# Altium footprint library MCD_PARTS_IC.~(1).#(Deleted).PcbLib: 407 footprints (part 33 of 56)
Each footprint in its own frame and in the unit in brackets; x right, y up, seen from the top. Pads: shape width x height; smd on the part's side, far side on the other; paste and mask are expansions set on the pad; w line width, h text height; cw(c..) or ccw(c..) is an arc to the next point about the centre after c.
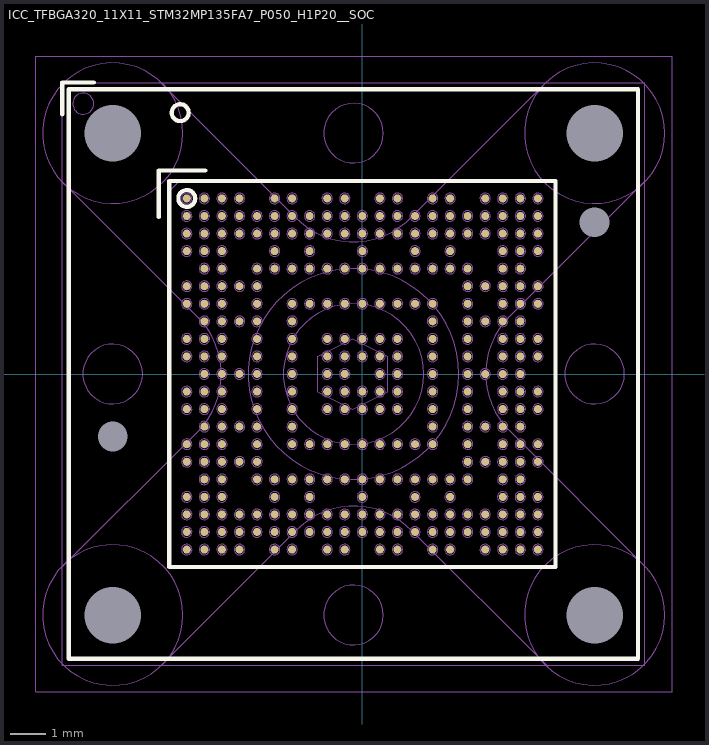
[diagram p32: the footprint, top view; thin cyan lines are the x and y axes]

## ICC_TFBGA320_11X11_STM32MP135FA7_P050_H1P20__SOCKET_IRONWOOD_SG-BGA-7074MF [mm] "MCD-02251"
height 1.2
pads (326):
  round 0.23 smd paste+0.025 mask+0.05: A1(-5,5) A2(-4.5,5) A3(-4,5) A4(-3.5,5) A6(-2.5,5) A7(-2,5) A9(-1,5) A10(-0.5,5) A12(0.5,5) A13(1,5) A15(2,5) A16(2.5,5) A18(3.5,5) A19(4,5) A20(4.5,5) A21(5,5) AA1(-5,-5) AA2(-4.5,-5) AA3(-4,-5) AA4(-3.5,-5) AA6(-2.5,-5) AA7(-2,-5) AA9(-1,-5) AA10(-0.5,-5) AA12(0.5,-5) AA13(1,-5) AA15(2,-5) AA16(2.5,-5) AA18(3.5,-5) AA19(4,-5) AA20(4.5,-5) AA21(5,-5) B1(-5,4.5) B2(-4.5,4.5) B3(-4,4.5) B4(-3.5,4.5) B5(-3,4.5) B6(-2.5,4.5) B7(-2,4.5) B8(-1.5,4.5) B9(-1,4.5) B10(-0.5,4.5) B11(0,4.5) B12(0.5,4.5) B13(1,4.5) B14(1.5,4.5) B15(2,4.5) B16(2.5,4.5) B17(3,4.5) B18(3.5,4.5) B19(4,4.5) B20(4.5,4.5) B21(5,4.5) C1(-5,4) C2(-4.5,4) C3(-4,4) C4(-3.5,4) C5(-3,4) C6(-2.5,4) C7(-2,4) C8(-1.5,4) C9(-1,4) C10(-0.5,4) C11(0,4) C12(0.5,4) C13(1,4) C14(1.5,4) C15(2,4) C16(2.5,4) C17(3,4) C18(3.5,4) C19(4,4) C20(4.5,4) C21(5,4) D1(-5,3.5) D2(-4.5,3.5) D3(-4,3.5) D6(-2.5,3.5) D8(-1.5,3.5) D11(0,3.5) D14(1.5,3.5) D16(2.5,3.5) D19(4,3.5) D20(4.5,3.5) D21(5,3.5) E2(-4.5,3) E3(-4,3) E5(-3,3) E6(-2.5,3) E7(-2,3) E8(-1.5,3) E9(-1,3) E10(-0.5,3) E11(0,3) E12(0.5,3) E13(1,3) E14(1.5,3) E15(2,3) E16(2.5,3) E17(3,3) E19(4,3) E20(4.5,3) F1(-5,2.5) F2(-4.5,2.5) F3(-4,2.5) F4(-3.5,2.5) F5(-3,2.5) F17(3,2.5) F18(3.5,2.5) F19(4,2.5) F20(4.5,2.5) F21(5,2.5) G1(-5,2) G2(-4.5,2) G3(-4,2) G5(-3,2) G7(-2,2) G8(-1.5,2) G9(-1,2) G10(-0.5,2) G11(0,2) G12(0.5,2) G13(1,2) G14(1.5,2) G15(2,2) G17(3,2) G19(4,2) G20(4.5,2) G21(5,2) H2(-4.5,1.5) H3(-4,1.5) H4(-3.5,1.5) H5(-3,1.5) H7(-2,1.5) H15(2,1.5) H17(3,1.5) H18(3.5,1.5) H19(4,1.5) H20(4.5,1.5) J1(-5,1) J2(-4.5,1) J3(-4,1) J5(-3,1) J7(-2,1) J9(-1,1) J10(-0.5,1) J11(0,1) J12(0.5,1) J13(1,1) J15(2,1) J17(3,1) J19(4,1) J20(4.5,1) J21(5,1) K1(-5,0.5) K2(-4.5,0.5) K3(-4,0.5) K5(-3,0.5) K7(-2,0.5) K9(-1,0.5) K10(-0.5,0.5) K11(0,0.5) K12(0.5,0.5) K13(1,0.5) K15(2,0.5) K17(3,0.5) K19(4,0.5) K20(4.5,0.5) K21(5,0.5) L2(-4.5,0) L3(-4,0) L4(-3.5,0) L5(-3,0) L7(-2,0) L9(-1,0) L10(-0.5,0) L12(0.5,0) L13(1,0) L15(2,0) L17(3,0) L18(3.5,0) L19(4,0) L20(4.5,0) M1(-5,-0.5) M2(-4.5,-0.5) M3(-4,-0.5) M5(-3,-0.5) M7(-2,-0.5) M9(-1,-0.5) M10(-0.5,-0.5) M11(0,-0.5) M12(0.5,-0.5) M13(1,-0.5) M15(2,-0.5) M17(3,-0.5) M19(4,-0.5) M20(4.5,-0.5) M21(5,-0.5) N1(-5,-1) N2(-4.5,-1) N3(-4,-1) N5(-3,-1) N7(-2,-1) N9(-1,-1) N10(-0.5,-1) N11(0,-1) N12(0.5,-1) N13(1,-1) N15(2,-1) N17(3,-1) N19(4,-1) N20(4.5,-1) N21(5,-1) P2(-4.5,-1.5) P3(-4,-1.5) P4(-3.5,-1.5) P5(-3,-1.5) P7(-2,-1.5) P15(2,-1.5) P17(3,-1.5) P18(3.5,-1.5) P19(4,-1.5) P20(4.5,-1.5) R1(-5,-2) R2(-4.5,-2) R3(-4,-2) R5(-3,-2) R7(-2,-2) R8(-1.5,-2) R9(-1,-2) R10(-0.5,-2) R11(0,-2) R12(0.5,-2) R13(1,-2) R14(1.5,-2) R15(2,-2) R17(3,-2) R19(4,-2) R20(4.5,-2) R21(5,-2) T1(-5,-2.5) T2(-4.5,-2.5) T3(-4,-2.5) T4(-3.5,-2.5) T5(-3,-2.5) T17(3,-2.5) T18(3.5,-2.5) T19(4,-2.5) T20(4.5,-2.5) T21(5,-2.5) U2(-4.5,-3) U3(-4,-3) U5(-3,-3) U6(-2.5,-3) U7(-2,-3) U8(-1.5,-3) U9(-1,-3) U10(-0.5,-3) U11(0,-3) U12(0.5,-3) U13(1,-3) U14(1.5,-3) U15(2,-3) U16(2.5,-3) U17(3,-3) U19(4,-3) U20(4.5,-3) V1(-5,-3.5) V2(-4.5,-3.5) V3(-4,-3.5) V6(-2.5,-3.5) V8(-1.5,-3.5) V11(-0.001,-3.5) V14(1.5,-3.5) V16(2.5,-3.5) V19(4,-3.5) V20(4.5,-3.5) V21(5,-3.5) W1(-5,-4) W2(-4.5,-4) W3(-4,-4) W4(-3.5,-4) W5(-3,-4) W6(-2.5,-4) W7(-2,-4) W8(-1.5,-4) W9(-1,-4) W10(-0.5,-4) W11(0,-4) W12(0.5,-4) W13(1,-4) W14(1.5,-4) W15(2,-4) W16(2.5,-4) W17(3,-4) W18(3.5,-4) W19(4,-4) W20(4.5,-4) W21(5,-4) Y1(-5,-4.5) Y2(-4.5,-4.5) Y3(-4,-4.5) Y4(-3.5,-4.5) Y5(-3,-4.5) Y6(-2.5,-4.5) Y7(-2,-4.5) Y8(-1.5,-4.5) Y9(-1,-4.5) Y10(-0.5,-4.5) Y11(0,-4.5) Y12(0.5,-4.5) Y13(1,-4.5) Y14(1.5,-4.5) Y15(2,-4.5) Y16(2.5,-4.5) Y17(3,-4.5) Y18(3.5,-4.5) Y19(4,-4.5) Y20(4.5,-4.5) Y21(5,-4.5)
  round 0 hole 0.85 unplated mask+0.05: NPTH1(6.615,4.32) NPTH2(-7.11,-1.785)
  round 0 hole 1.61 unplated mask+0.05: PTH1(-7.11,6.86) PTH2(6.615,6.86) PTH3(6.615,-6.865) PTH4(-7.11,-6.865)
Top Layer:
  lines w0.1: 4.5,2.5 ccw(c4.5,2.5) 4.5,2.5
Top Overlay:
  circle w0.12: c-5,5 r0.24
  circle w0.12: c-5.187,7.444 r0.24
  lines w0.12: -8.55,7.4 -8.55,8.3 -7.65,8.3 ; -5.8,4.475 -5.8,5.8 -4.475,5.8 ; -8.36,-8.112 -8.36,8.11 7.85,8.11 7.85,-8.112 -8.36,-8.112 ; -5.5,-5.5 -5.5,5.5 5.5,5.5 5.5,-5.5 -5.5,-5.5
Bottom Overlay:
  circle w0.12: c-7.11,-6.865 r2
  circle w0.12: c6.615,-6.865 r2
  circle w0.12: c6.615,6.86 r2
  circle w0.12: c-7.11,6.86 r2
  circle w0.12: c-0.25,0 r2
  lines w0.12: -8.575,-5.525 -4.723,-1.673 ; -8.575,5.5 -4.75,1.675 cw(c-6.312,-0.013) -4.722,-1.674 ; -5.775,8.325 -1.923,4.473 ; -5.75,-8.325 -1.925,-4.5 cw(c-0.237,-6.062) 1.424,-4.472 ; -1.924,4.472 ccw(c-0.263,6.063) 1.425,4.5 5.25,8.325 ; 1.423,-4.473 5.275,-8.325 ; 4.222,1.674 ccw(c5.813,0.013) 4.25,-1.675 8.075,-5.5 ; 4.223,1.673 8.075,5.525
M8-Bottom Info:
  circle w0.01: c-0.25,0 r2
  circle w0.01: c-7.11,6.86 r2
  circle w0.01: c6.615,6.86 r2
  circle w0.01: c6.615,-6.865 r2
  circle w0.01: c-7.11,-6.865 r2
  lines w0.01: -8.575,-5.525 -4.723,-1.673 ; -8.575,5.5 -4.75,1.675 cw(c-6.312,-0.013) -4.722,-1.674 ; -5.775,8.325 -1.923,4.473 ; -5.75,-8.325 -1.925,-4.5 cw(c-0.237,-6.062) 1.424,-4.472 ; -1.924,4.472 ccw(c-0.263,6.063) 1.425,4.5 5.25,8.325 ; 1.423,-4.473 5.275,-8.325 ; 4.222,1.674 ccw(c5.813,0.013) 4.25,-1.675 8.075,-5.5 ; 4.223,1.673 8.075,5.525
  text "Max Height :" at -3.9,2.475 h1.52
  text "1.5mm" at -2.35,-3.25 h1.52
M14-Top Assembly:
  drawing of 345 lines, arcs and shapes, not listed
  text "A1" at -5.25,4.8 h0.4
  text "'.Designator'" at 0,0 h0.75
M15-Bottom Assembly:
  circle w0.01: c-7.11,6.86 r2
  circle w0.01: c-0.25,0 r2
  circle w0.01: c6.615,6.86 r2
  circle w0.01: c6.615,-6.865 r2
  circle w0.01: c-7.11,-6.865 r2
  lines w0.01: -8.575,-5.525 -4.723,-1.673 ; -8.575,5.5 -4.75,1.675 cw(c-6.312,-0.013) -4.722,-1.674 ; -5.775,8.325 -1.923,4.473 ; -5.75,-8.325 -1.925,-4.5 cw(c-0.237,-6.062) 1.424,-4.472 ; -1.924,4.472 ccw(c-0.263,6.063) 1.425,4.5 5.25,8.325 ; 1.423,-4.473 5.275,-8.325 ; 4.222,1.674 ccw(c5.813,0.013) 4.25,-1.675 8.075,-5.5 ; 4.223,1.673 8.075,5.525
M16-Top Courtyard:
  lines w0.01: -8.55,-8.3 8.05,-8.3 8.05,8.3 -8.55,8.3 -8.55,-8.3
M17-Bottom Courtyard:
  lines w0.01: -9.3,-9.05 -9.3,9.05 8.825,9.05 8.825,-9.05 -9.3,-9.05
3D body: height 6, standoff 5, extent -7.953,-0.848 -6.26,0.849
3D body: height 6, standoff 5, extent -1.093,6.012 0.6,7.709
3D body: height 6, standoff 5, extent 5.772,-0.848 7.465,0.849
3D body: height 6, standoff 5, extent -1.093,-7.713 0.6,-6.017
3D body: height 8.25, standoff 5, extent -3.25,-3 2.75,3
3D body: height 5, standoff 0, extent -8.362,-8.112 7.863,8.113
3D body: height 8.26, standoff 8.25, extent -1.25,-1 0.75,1
3D body: height 1.11, standoff 1.1, extent -5.298,4.701 -4.7,5.3
3D body: height 0.36, standoff -0.04, extent 4.3,-5.197 4.699,-4.803
3D body: height 0.36, standoff -0.04, extent 4.8,-4.697 5.199,-4.303
3D body: height 0.36, standoff -0.04, extent 3.8,-5.197 4.199,-4.803
3D body: height 0.36, standoff -0.04, extent 0.801,-4.697 1.2,-4.303
3D body: height 0.36, standoff -0.04, extent 1.301,-4.697 1.7,-4.303
3D body: height 0.36, standoff -0.04, extent 2.3,-4.697 2.699,-4.303
3D body: height 0.36, standoff -0.04, extent 2.3,-5.197 2.7,-4.803
3D body: height 0.36, standoff -0.04, extent 2.8,-4.697 3.199,-4.303
3D body: height 0.36, standoff -0.04, extent -4.199,-5.197 -3.8,-4.803
3D body: height 0.36, standoff -0.04, extent -4.199,-4.697 -3.8,-4.303
3D body: height 0.36, standoff -0.04, extent -2.199,-4.697 -1.8,-4.303
3D body: height 0.36, standoff -0.04, extent -1.699,-4.697 -1.3,-4.303
3D body: height 0.36, standoff -0.04, extent -0.699,-5.197 -0.3,-4.803
3D body: height 0.36, standoff -0.04, extent 4.3,-4.697 4.699,-4.303
3D body: height 0.36, standoff -0.04, extent 3.8,-4.697 4.199,-4.303
3D body: height 0.36, standoff -0.04, extent 3.3,-5.197 3.7,-4.803
3D body: height 0.36, standoff -0.04, extent -1.199,-5.197 -0.8,-4.803
3D body: height 0.36, standoff -0.04, extent -0.199,-4.697 0.2,-4.303
3D body: height 0.36, standoff -0.04, extent 0.3,-5.197 0.7,-4.803
3D body: height 0.36, standoff -0.04, extent 1.8,-5.197 2.199,-4.803
3D body: height 0.36, standoff -0.04, extent -5.199,-5.197 -4.8,-4.803
3D body: height 0.36, standoff -0.04, extent -4.699,-5.197 -4.3,-4.803
3D body: height 0.36, standoff -0.04, extent -3.699,-5.197 -3.3,-4.803
3D body: height 0.36, standoff -0.04, extent -2.699,-5.197 -2.3,-4.803
3D body: height 0.36, standoff -0.04, extent -2.199,-5.197 -1.8,-4.803
3D body: height 0.36, standoff -0.04, extent 4.8,-5.197 5.199,-4.803
3D body: height 0.36, standoff -0.04, extent 3.3,-4.697 3.699,-4.303
3D body: height 0.36, standoff -0.04, extent -1.199,-4.697 -0.8,-4.303
3D body: height 0.36, standoff -0.04, extent -0.699,-4.697 -0.3,-4.303
3D body: height 0.36, standoff -0.04, extent 0.3,-4.697 0.7,-4.303
3D body: height 0.36, standoff -0.04, extent 0.801,-5.197 1.2,-4.803
3D body: height 0.36, standoff -0.04, extent 1.8,-4.697 2.2,-4.303
3D body: height 0.36, standoff -0.04, extent -5.199,-4.697 -4.8,-4.303
3D body: height 0.36, standoff -0.04, extent -4.699,-4.697 -4.3,-4.303
3D body: height 0.36, standoff -0.04, extent -3.699,-4.697 -3.3,-4.303
3D body: height 0.36, standoff -0.04, extent -3.199,-4.697 -2.8,-4.303
3D body: height 0.36, standoff -0.04, extent -2.699,-4.697 -2.3,-4.303
3D body: height 0.36, standoff -0.04, extent 4.8,-3.697 5.199,-3.303
3D body: height 0.36, standoff -0.04, extent 4.3,-3.697 4.699,-3.303
3D body: height 0.36, standoff -0.04, extent 3.8,-3.697 4.199,-3.303
3D body: height 0.36, standoff -0.04, extent 4.8,-4.197 5.199,-3.803
3D body: height 0.36, standoff -0.04, extent 4.3,-4.197 4.699,-3.803
3D body: height 0.36, standoff -0.04, extent -0.2,-3.697 0.2,-3.303
3D body: height 0.36, standoff -0.04, extent 0.8,-4.197 1.2,-3.803
3D body: height 0.36, standoff -0.04, extent 2.3,-3.697 2.699,-3.303
3D body: height 0.36, standoff -0.04, extent -4.699,-3.697 -4.3,-3.303
3D body: height 0.36, standoff -0.04, extent -4.199,-3.697 -3.8,-3.303
3D body: height 0.36, standoff -0.04, extent -3.199,-4.197 -2.8,-3.803
3D body: height 0.36, standoff -0.04, extent -1.699,-3.697 -1.3,-3.303
3D body: height 0.36, standoff -0.04, extent 4.3,-2.697 4.699,-2.303
3D body: height 0.36, standoff -0.04, extent 3.8,-2.697 4.199,-2.303
3D body: height 0.36, standoff -0.04, extent 4.3,-3.197 4.699,-2.803
3D body: height 0.36, standoff -0.04, extent 3.8,-3.197 4.2,-2.803
3D body: height 0.36, standoff -0.04, extent 2.801,-3.197 3.2,-2.803
3D body: height 0.36, standoff -0.04, extent -1.199,-3.197 -0.8,-2.803
3D body: height 0.36, standoff -0.04, extent 0.801,-3.197 1.2,-2.803
3D body: height 0.36, standoff -0.04, extent 1.3,-3.197 1.7,-2.803
3D body: height 0.36, standoff -0.04, extent 1.8,-3.197 2.2,-2.803
3D body: height 0.36, standoff -0.04, extent 2.3,-3.197 2.699,-2.803
3D body: height 0.36, standoff -0.04, extent -4.699,-3.197 -4.3,-2.803
3D body: height 0.36, standoff -0.04, extent -4.199,-3.197 -3.8,-2.803
3D body: height 0.36, standoff -0.04, extent -3.199,-3.197 -2.8,-2.803
3D body: height 0.36, standoff -0.04, extent -2.199,-3.197 -1.8,-2.803
3D body: height 0.36, standoff -0.04, extent -1.699,-3.197 -1.3,-2.803
3D body: height 0.36, standoff -0.04, extent 4.8,-2.697 5.199,-2.303
3D body: height 0.36, standoff -0.04, extent 4.8,-2.197 5.199,-1.803
3D body: height 0.36, standoff -0.04, extent 4.3,-2.197 4.699,-1.803
3D body: height 0.36, standoff -0.04, extent 3.8,-2.197 4.199,-1.803
3D body: height 0.36, standoff -0.04, extent 2.8,-2.197 3.2,-1.803
3D body: height 0.36, standoff -0.04, extent -0.199,-2.197 0.2,-1.803
3D body: height 0.36, standoff -0.04, extent 0.301,-2.197 0.7,-1.803
3D body: height 0.36, standoff -0.04, extent 0.801,-2.197 1.2,-1.803
3D body: height 0.36, standoff -0.04, extent 1.301,-2.197 1.7,-1.803
3D body: height 0.36, standoff -0.04, extent 1.8,-2.197 2.2,-1.803
3D body: height 0.36, standoff -0.04, extent -4.699,-2.197 -4.3,-1.803
3D body: height 0.36, standoff -0.04, extent -4.199,-2.197 -3.8,-1.803
3D body: height 0.36, standoff -0.04, extent -3.199,-2.697 -2.8,-2.303
3D body: height 0.36, standoff -0.04, extent -3.199,-2.197 -2.8,-1.803
3D body: height 0.36, standoff -0.04, extent -0.699,-2.197 -0.3,-1.803
3D body: height 0.36, standoff -0.04, extent 4.301,-1.197 4.7,-0.803
3D body: height 0.36, standoff -0.04, extent 3.801,-1.197 4.2,-0.803
3D body: height 0.36, standoff -0.04, extent 4.301,-1.697 4.7,-1.303
3D body: height 0.36, standoff -0.04, extent 3.801,-1.697 4.2,-1.303
3D body: height 0.36, standoff -0.04, extent 2.801,-1.197 3.2,-0.803
3D body: height 0.36, standoff -0.04, extent -2.199,-1.197 -1.8,-0.803
3D body: height 0.36, standoff -0.04, extent 1.801,-1.197 2.2,-0.803
3D body: height 0.36, standoff -0.04, extent -5.199,-1.197 -4.8,-0.803
3D body: height 0.36, standoff -0.04, extent -4.699,-1.197 -4.3,-0.803
3D body: height 0.36, standoff -0.04, extent -4.199,-1.197 -3.8,-0.803
3D body: height 0.36, standoff -0.04, extent -3.199,-1.197 -2.8,-0.803
3D body: height 0.36, standoff -0.04, extent -2.199,-1.697 -1.8,-1.303
3D body: height 0.36, standoff -0.04, extent 4.801,-1.197 5.2,-0.803
3D body: height 0.36, standoff -0.04, extent 4.8,-0.697 5.2,-0.303
3D body: height 0.36, standoff -0.04, extent 4.301,-0.697 4.7,-0.303
3D body: height 0.36, standoff -0.04, extent 3.801,-0.697 4.2,-0.303
3D body: height 0.36, standoff -0.04, extent 2.801,-0.697 3.2,-0.303
3D body: height 0.36, standoff -0.04, extent 1.801,-0.697 2.2,-0.303
3D body: height 0.36, standoff -0.04, extent -5.199,-0.697 -4.8,-0.303
3D body: height 0.36, standoff -0.04, extent -4.699,-0.697 -4.3,-0.303
3D body: height 0.36, standoff -0.04, extent -4.199,-0.697 -3.8,-0.303
3D body: height 0.36, standoff -0.04, extent -3.199,-0.697 -2.8,-0.303
3D body: height 0.36, standoff -0.04, extent -2.199,-0.697 -1.8,-0.303
3D body: height 0.36, standoff -0.04, extent 4.3,-0.197 4.699,0.197
3D body: height 0.36, standoff -0.04, extent 3.8,-0.197 4.2,0.197
3D body: height 0.36, standoff -0.04, extent 4.3,0.303 4.699,0.697
3D body: height 0.36, standoff -0.04, extent 3.8,0.303 4.2,0.697
3D body: height 0.36, standoff -0.04, extent 2.8,0.303 3.2,0.697
3D body: height 0.36, standoff -0.04, extent -1.199,-0.197 -0.8,0.197
3D body: height 0.36, standoff -0.04, extent 3.3,-0.197 3.699,0.197
3D body: height 0.36, standoff -0.04, extent -5.199,0.303 -4.8,0.697
3D body: height 0.36, standoff -0.04, extent -4.699,0.303 -4.3,0.697
3D body: height 0.36, standoff -0.04, extent -4.199,0.303 -3.8,0.697
3D body: height 0.36, standoff -0.04, extent -3.199,0.303 -2.8,0.697
3D body: height 0.36, standoff -0.04, extent -2.199,0.303 -1.8,0.697
3D body: height 0.36, standoff -0.04, extent 4.8,0.303 5.199,0.697
3D body: height 0.36, standoff -0.04, extent 4.8,0.803 5.199,1.197
3D body: height 0.36, standoff -0.04, extent 4.3,0.803 4.699,1.197
3D body: height 0.36, standoff -0.04, extent 3.8,0.803 4.2,1.197
3D body: height 0.36, standoff -0.04, extent 2.801,0.803 3.2,1.197
3D body: height 0.36, standoff -0.04, extent -1.199,0.803 -0.8,1.197
3D body: height 0.36, standoff -0.04, extent -0.699,0.803 -0.3,1.197
3D body: height 0.36, standoff -0.04, extent -0.2,0.803 0.2,1.197
3D body: height 0.36, standoff -0.04, extent 0.301,0.803 0.7,1.197
3D body: height 0.36, standoff -0.04, extent 1.8,0.803 2.2,1.197
3D body: height 0.36, standoff -0.04, extent -5.199,0.803 -4.8,1.197
3D body: height 0.36, standoff -0.04, extent -4.699,0.803 -4.3,1.197
3D body: height 0.36, standoff -0.04, extent -4.199,0.803 -3.8,1.197
3D body: height 0.36, standoff -0.04, extent -3.199,0.803 -2.8,1.197
3D body: height 0.36, standoff -0.04, extent -2.199,0.803 -1.8,1.197
3D body: height 0.36, standoff -0.04, extent 4.301,1.303 4.7,1.697
3D body: height 0.36, standoff -0.04, extent 4.801,1.803 5.2,2.197
3D body: height 0.36, standoff -0.04, extent 4.301,1.803 4.7,2.197
3D body: height 0.36, standoff -0.04, extent 3.801,1.803 4.2,2.197
3D body: height 0.36, standoff -0.04, extent 2.801,1.803 3.2,2.197
3D body: height 0.36, standoff -0.04, extent -1.699,1.804 -1.3,2.198
3D body: height 0.36, standoff -0.04, extent -1.199,1.804 -0.8,2.197
3D body: height 0.36, standoff -0.04, extent -0.699,1.804 -0.3,2.197
3D body: height 0.36, standoff -0.04, extent -0.199,1.804 0.2,2.197
3D body: height 0.36, standoff -0.04, extent 0.301,1.803 0.7,2.197
3D body: height 0.36, standoff -0.04, extent -5.199,1.803 -4.8,2.197
3D body: height 0.36, standoff -0.04, extent -4.699,1.803 -4.3,2.197
3D body: height 0.36, standoff -0.04, extent -4.199,1.803 -3.8,2.197
3D body: height 0.36, standoff -0.04, extent -3.199,1.803 -2.8,2.197
3D body: height 0.36, standoff -0.04, extent -2.199,1.804 -1.8,2.197
3D body: height 0.36, standoff -0.04, extent 4.801,2.303 5.2,2.697
3D body: height 0.36, standoff -0.04, extent 2.801,2.803 3.2,3.197
3D body: height 0.36, standoff -0.04, extent 2.301,2.803 2.7,3.197
3D body: height 0.36, standoff -0.04, extent 1.801,2.803 2.2,3.197
3D body: height 0.36, standoff -0.04, extent 1.301,2.803 1.7,3.197
3D body: height 0.36, standoff -0.04, extent -2.199,2.803 -1.8,3.197
3D body: height 0.36, standoff -0.04, extent -1.699,2.803 -1.3,3.197
3D body: height 0.36, standoff -0.04, extent -0.199,2.803 0.2,3.197
3D body: height 0.36, standoff -0.04, extent 0.301,2.803 0.7,3.197
3D body: height 0.36, standoff -0.04, extent 0.801,2.803 1.2,3.197
3D body: height 0.36, standoff -0.04, extent -5.199,2.303 -4.8,2.697
3D body: height 0.36, standoff -0.04, extent -4.699,2.303 -4.3,2.697
3D body: height 0.36, standoff -0.04, extent -4.199,2.303 -3.8,2.697
3D body: height 0.36, standoff -0.04, extent -3.199,2.803 -2.8,3.197
3D body: height 0.36, standoff -0.04, extent -2.699,2.803 -2.3,3.197
3D body: height 0.36, standoff -0.04, extent 3.801,2.803 4.2,3.197
3D body: height 0.36, standoff -0.04, extent 4.301,2.803 4.7,3.197
3D body: height 0.36, standoff -0.04, extent 4.301,3.303 4.7,3.697
3D body: height 0.36, standoff -0.04, extent 3.801,3.303 4.2,3.697
3D body: height 0.36, standoff -0.04, extent 4.801,3.303 5.2,3.697
3D body: height 0.36, standoff -0.04, extent -1.199,2.803 -0.8,3.197
3D body: height 0.36, standoff -0.04, extent -0.199,3.303 0.2,3.697
3D body: height 0.36, standoff -0.04, extent -0.699,2.803 -0.3,3.197
3D body: height 0.36, standoff -0.04, extent 1.301,3.303 1.7,3.697
3D body: height 0.36, standoff -0.04, extent 2.301,3.303 2.7,3.697
3D body: height 0.36, standoff -0.04, extent -5.199,3.303 -4.8,3.697
3D body: height 0.36, standoff -0.04, extent -4.699,3.303 -4.3,3.697
3D body: height 0.36, standoff -0.04, extent -4.199,3.303 -3.8,3.697
3D body: height 0.36, standoff -0.04, extent -2.699,3.303 -2.3,3.697
3D body: height 0.36, standoff -0.04, extent -1.699,3.303 -1.3,3.697
3D body: height 0.36, standoff -0.04, extent 4.801,4.303 5.2,4.697
3D body: height 0.36, standoff -0.04, extent 4.301,4.303 4.7,4.697
3D body: height 0.36, standoff -0.04, extent 3.801,4.303 4.2,4.697
3D body: height 0.36, standoff -0.04, extent 3.301,4.303 3.7,4.697
3D body: height 0.36, standoff -0.04, extent 2.801,4.303 3.2,4.697
3D body: height 0.36, standoff -0.04, extent -2.699,4.303 -2.3,4.697
3D body: height 0.36, standoff -0.04, extent -0.699,4.803 -0.3,5.197
3D body: height 0.36, standoff -0.04, extent 1.301,4.303 1.7,4.697
3D body: height 0.36, standoff -0.04, extent 1.801,4.303 2.2,4.697
3D body: height 0.36, standoff -0.04, extent 2.301,4.303 2.7,4.697
3D body: height 0.36, standoff -0.04, extent -5.199,4.303 -4.8,4.697
3D body: height 0.36, standoff -0.04, extent -4.699,4.303 -4.3,4.697
3D body: height 0.36, standoff -0.04, extent -4.199,4.303 -3.8,4.697
3D body: height 0.36, standoff -0.04, extent -3.699,4.303 -3.3,4.697
3D body: height 0.36, standoff -0.04, extent -3.199,4.303 -2.8,4.697
3D body: height 0.36, standoff -0.04, extent -2.699,4.803 -2.3,5.197
3D body: height 0.36, standoff -0.04, extent -3.699,4.803 -3.3,5.197
3D body: height 0.36, standoff -0.04, extent -4.199,4.803 -3.8,5.197
3D body: height 0.36, standoff -0.04, extent -4.699,4.803 -4.3,5.197
3D body: height 0.36, standoff -0.04, extent -5.199,4.803 -4.8,5.197
3D body: height 0.36, standoff -0.04, extent 1.801,4.803 2.2,5.197
3D body: height 0.36, standoff -0.04, extent 0.801,4.803 1.2,5.197
3D body: height 0.36, standoff -0.04, extent 0.301,4.803 0.7,5.197
3D body: height 0.36, standoff -0.04, extent -2.199,4.803 -1.8,5.197
3D body: height 0.36, standoff -0.04, extent -1.199,4.803 -0.8,5.197
3D body: height 0.36, standoff -0.04, extent 2.301,4.803 2.7,5.197
3D body: height 0.36, standoff -0.04, extent 3.301,4.803 3.7,5.197
3D body: height 0.36, standoff -0.04, extent 3.801,4.803 4.2,5.197
3D body: height 0.36, standoff -0.04, extent 4.301,4.803 4.7,5.197
3D body: height 1.1, standoff 0.3, extent -5.5,-5.524 5.5,5.524
3D body: height 0.36, standoff -0.04, extent 4.801,4.803 5.2,5.197
3D body: height 0.36, standoff -0.04, extent 0.801,4.303 1.2,4.697
3D body: height 0.36, standoff -0.04, extent 0.301,4.303 0.7,4.697
3D body: height 0.36, standoff -0.04, extent -0.199,4.303 0.2,4.697
3D body: height 0.36, standoff -0.04, extent -0.699,4.303 -0.3,4.697
3D body: height 0.36, standoff -0.04, extent -1.199,4.303 -0.8,4.697
3D body: height 0.36, standoff -0.04, extent -1.699,4.303 -1.3,4.697
3D body: height 0.36, standoff -0.04, extent -2.199,4.303 -1.8,4.697
3D body: height 0.36, standoff -0.04, extent -5.199,3.803 -4.8,4.197
3D body: height 0.36, standoff -0.04, extent -4.699,3.803 -4.3,4.197
3D body: height 0.36, standoff -0.04, extent -4.199,3.803 -3.8,4.197
3D body: height 0.36, standoff -0.04, extent -3.699,3.803 -3.3,4.197
3D body: height 0.36, standoff -0.04, extent -3.199,3.803 -2.8,4.197
3D body: height 0.36, standoff -0.04, extent -2.699,3.803 -2.3,4.197
3D body: height 0.36, standoff -0.04, extent -2.199,3.803 -1.8,4.197
3D body: height 0.36, standoff -0.04, extent -1.699,3.803 -1.3,4.197
3D body: height 0.36, standoff -0.04, extent -1.199,3.803 -0.8,4.197
3D body: height 0.36, standoff -0.04, extent -0.699,3.803 -0.3,4.197
3D body: height 0.36, standoff -0.04, extent -0.199,3.803 0.2,4.197
3D body: height 0.36, standoff -0.04, extent 0.301,3.803 0.7,4.197
3D body: height 0.36, standoff -0.04, extent 0.801,3.803 1.2,4.197
3D body: height 0.36, standoff -0.04, extent 1.301,3.803 1.7,4.197
3D body: height 0.36, standoff -0.04, extent 1.801,3.803 2.2,4.197
3D body: height 0.36, standoff -0.04, extent 2.301,3.803 2.7,4.197
3D body: height 0.36, standoff -0.04, extent 2.801,3.803 3.2,4.197
3D body: height 0.36, standoff -0.04, extent 3.301,3.803 3.7,4.197
3D body: height 0.36, standoff -0.04, extent 3.801,3.803 4.2,4.197
3D body: height 0.36, standoff -0.04, extent 4.301,3.803 4.7,4.197
3D body: height 0.36, standoff -0.04, extent 4.801,3.803 5.2,4.197
3D body: height 0.36, standoff -0.04, extent -4.699,2.803 -4.3,3.197
3D body: height 0.36, standoff -0.04, extent -4.199,2.803 -3.8,3.197
3D body: height 0.36, standoff -0.04, extent 4.301,2.303 4.7,2.697
3D body: height 0.36, standoff -0.04, extent 3.801,2.303 4.2,2.697
3D body: height 0.36, standoff -0.04, extent 3.301,2.303 3.7,2.697
3D body: height 0.36, standoff -0.04, extent 2.801,2.303 3.2,2.697
3D body: height 0.36, standoff -0.04, extent -3.199,2.303 -2.8,2.697
3D body: height 0.36, standoff -0.04, extent -3.699,2.303 -3.3,2.697
3D body: height 0.36, standoff -0.04, extent 0.801,1.803 1.2,2.197
3D body: height 0.36, standoff -0.04, extent 1.301,1.803 1.7,2.197
3D body: height 0.36, standoff -0.04, extent 1.801,1.803 2.2,2.197
3D body: height 0.36, standoff -0.04, extent 3.801,1.303 4.2,1.697
3D body: height 0.36, standoff -0.04, extent 3.301,1.303 3.7,1.697
3D body: height 0.36, standoff -0.04, extent 2.801,1.304 3.2,1.697
3D body: height 0.36, standoff -0.04, extent 1.801,1.304 2.2,1.697
3D body: height 0.36, standoff -0.04, extent -2.199,1.303 -1.8,1.697
3D body: height 0.36, standoff -0.04, extent -3.199,1.303 -2.8,1.697
3D body: height 0.36, standoff -0.04, extent -3.699,1.303 -3.3,1.697
3D body: height 0.36, standoff -0.04, extent -4.199,1.303 -3.8,1.697
3D body: height 0.36, standoff -0.04, extent -4.699,1.303 -4.3,1.697
3D body: height 0.36, standoff -0.04, extent 0.801,0.803 1.2,1.197
3D body: height 0.36, standoff -0.04, extent 2.8,-0.197 3.2,0.197
3D body: height 0.36, standoff -0.04, extent 1.8,-0.197 2.2,0.197
3D body: height 0.36, standoff -0.04, extent 1.8,0.303 2.2,0.697
3D body: height 0.36, standoff -0.04, extent 0.801,0.303 1.2,0.697
3D body: height 0.36, standoff -0.04, extent 0.301,0.303 0.7,0.697
3D body: height 0.36, standoff -0.04, extent -0.199,0.303 0.2,0.697
3D body: height 0.36, standoff -0.04, extent -0.699,0.303 -0.3,0.697
3D body: height 0.36, standoff -0.04, extent -1.199,0.303 -0.8,0.697
3D body: height 0.36, standoff -0.04, extent -0.699,-0.197 -0.3,0.197
3D body: height 0.36, standoff -0.04, extent 0.301,-0.197 0.7,0.197
3D body: height 0.36, standoff -0.04, extent 0.801,-0.197 1.2,0.197
3D body: height 0.36, standoff -0.04, extent 0.801,-0.697 1.2,-0.303
3D body: height 0.36, standoff -0.04, extent 0.301,-0.697 0.7,-0.303
3D body: height 0.36, standoff -0.04, extent -0.199,-0.697 0.2,-0.303
3D body: height 0.36, standoff -0.04, extent -0.699,-0.697 -0.3,-0.303
3D body: height 0.36, standoff -0.04, extent -1.199,-0.697 -0.8,-0.303
3D body: height 0.36, standoff -0.04, extent -4.699,-0.197 -4.3,0.197
3D body: height 0.36, standoff -0.04, extent -4.199,-0.197 -3.8,0.197
3D body: height 0.36, standoff -0.04, extent -3.699,-0.197 -3.3,0.197
3D body: height 0.36, standoff -0.04, extent -3.199,-0.197 -2.8,0.197
3D body: height 0.36, standoff -0.04, extent -2.199,-0.197 -1.8,0.197
3D body: height 0.36, standoff -0.04, extent 0.801,-1.197 1.2,-0.803
3D body: height 0.36, standoff -0.04, extent 0.301,-1.197 0.7,-0.803
3D body: height 0.36, standoff -0.04, extent -0.199,-1.197 0.2,-0.803
3D body: height 0.36, standoff -0.04, extent -0.699,-1.197 -0.3,-0.803
3D body: height 0.36, standoff -0.04, extent -1.199,-1.197 -0.8,-0.803
3D body: height 0.36, standoff -0.04, extent -4.699,-1.697 -4.3,-1.303
3D body: height 0.36, standoff -0.04, extent -4.199,-1.697 -3.8,-1.303
3D body: height 0.36, standoff -0.04, extent -3.699,-1.697 -3.3,-1.303
3D body: height 0.36, standoff -0.04, extent -3.199,-1.697 -2.8,-1.303
3D body: height 0.36, standoff -0.04, extent 1.801,-1.697 2.2,-1.303
3D body: height 0.36, standoff -0.04, extent 2.801,-1.697 3.2,-1.303
3D body: height 0.36, standoff -0.04, extent 3.301,-1.697 3.7,-1.303
3D body: height 0.36, standoff -0.04, extent 3.3,-2.697 3.699,-2.303
3D body: height 0.36, standoff -0.04, extent 2.8,-2.697 3.199,-2.303
3D body: height 0.36, standoff -0.04, extent 0.301,-3.197 0.7,-2.803
3D body: height 0.36, standoff -0.04, extent -0.199,-3.197 0.2,-2.803
3D body: height 0.36, standoff -0.04, extent -0.699,-3.197 -0.3,-2.803
3D body: height 0.36, standoff -0.04, extent -1.199,-2.197 -0.8,-1.803
3D body: height 0.36, standoff -0.04, extent -1.699,-2.197 -1.3,-1.803
3D body: height 0.36, standoff -0.04, extent -2.199,-2.197 -1.8,-1.803
3D body: height 0.36, standoff -0.04, extent -2.699,-3.197 -2.3,-2.803
3D body: height 0.36, standoff -0.04, extent -5.199,-2.197 -4.8,-1.803
3D body: height 0.36, standoff -0.04, extent -5.199,-2.697 -4.8,-2.303
3D body: height 0.36, standoff -0.04, extent -4.699,-2.697 -4.3,-2.303
3D body: height 0.36, standoff -0.04, extent -4.199,-2.697 -3.8,-2.303
3D body: height 0.36, standoff -0.04, extent -3.699,-2.697 -3.3,-2.303
3D body: height 0.36, standoff -0.04, extent 3.8,-4.197 4.2,-3.803
3D body: height 0.36, standoff -0.04, extent 3.3,-4.197 3.7,-3.803
3D body: height 0.36, standoff -0.04, extent 2.8,-4.197 3.2,-3.803
3D body: height 0.36, standoff -0.04, extent 2.3,-4.197 2.7,-3.803
3D body: height 0.36, standoff -0.04, extent 1.8,-4.197 2.2,-3.803
3D body: height 0.36, standoff -0.04, extent 1.3,-3.697 1.7,-3.303
3D body: height 0.36, standoff -0.04, extent 1.301,-4.197 1.7,-3.803
3D body: height 0.36, standoff -0.04, extent 0.301,-4.197 0.7,-3.803
3D body: height 0.36, standoff -0.04, extent -0.199,-4.197 0.2,-3.803
3D body: height 0.36, standoff -0.04, extent -0.699,-4.197 -0.3,-3.803
3D body: height 0.36, standoff -0.04, extent -1.199,-4.197 -0.8,-3.803
3D body: height 0.36, standoff -0.04, extent -1.699,-4.197 -1.3,-3.803
3D body: height 0.36, standoff -0.04, extent -2.199,-4.197 -1.8,-3.803
3D body: height 0.36, standoff -0.04, extent -2.699,-3.697 -2.3,-3.303
3D body: height 0.36, standoff -0.04, extent -2.699,-4.197 -2.3,-3.803
3D body: height 0.36, standoff -0.04, extent -3.699,-4.197 -3.3,-3.803
3D body: height 0.36, standoff -0.04, extent -5.199,-3.697 -4.8,-3.303
3D body: height 0.36, standoff -0.04, extent -5.199,-4.197 -4.8,-3.803
3D body: height 0.36, standoff -0.04, extent -4.699,-4.197 -4.3,-3.803
3D body: height 0.36, standoff -0.04, extent -4.199,-4.197 -3.8,-3.803
3D body: height -1.7, standoff -5.7, extent -9.11,6.86 -5.11,8.86
3D body: height -1.7, standoff -5.7, extent -9.11,4.86 -5.11,6.86
3D body: height -1.7, standoff -5.7, extent 4.615,4.86 8.615,6.86
3D body: height -1.7, standoff -5.7, extent 4.615,6.86 8.615,8.86
3D body: height -1.7, standoff -5.7, extent 4.615,-8.865 8.615,-6.865
3D body: height -1.7, standoff -5.7, extent 4.615,-6.865 8.615,-4.865
3D body: height -1.7, standoff -5.7, extent -9.11,-8.865 -5.11,-6.865
3D body: height -1.7, standoff -5.7, extent -9.11,-6.865 -5.11,-4.865
3D body: height -1.7, standoff -3.2, extent -2.25,-2 1.75,0
3D body: height -1.7, standoff -3.2, extent -2.25,0 1.75,2
3D body: height -3.2, standoff -5.7, extent -8.75,-8.625 8.615,8.414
